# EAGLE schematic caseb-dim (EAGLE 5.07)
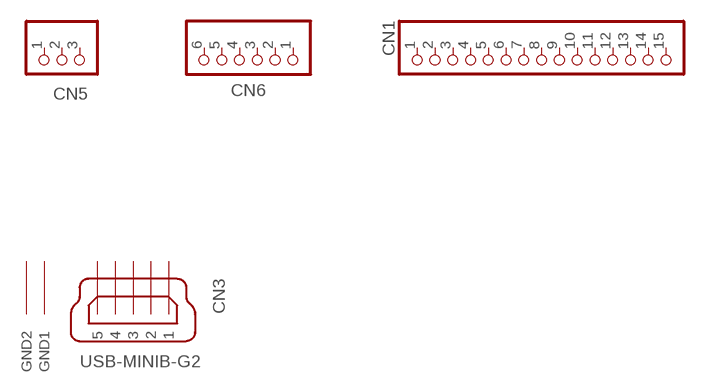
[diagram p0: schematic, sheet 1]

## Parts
CN1  PINHDR15  [PINHDRX15]
CN3  USB-MINIB-G2  [USB-MINIBV]
CN5  PINHDR3  [PINHDR1X3]
CN6  PINHDR6  [PINHDR1X6]
Unconnected: CN1.1 CN1.2 CN1.3 CN1.4 CN1.5 CN1.6 CN1.7 CN1.8 CN1.9 CN1.10 CN1.11 CN1.12 CN1.13 CN1.14 CN1.15 CN3.1 CN3.2 CN3.3 CN3.4 CN3.5 CN3.M1(GND1) CN3.M2(GND2) CN5.1 CN5.2 CN5.3 CN6.1 CN6.2 CN6.3 CN6.4 CN6.5 CN6.6

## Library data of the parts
CN1 = SRT162-010:PINHDR15
CN3 = SRT162-010:USB-MINIB-G2
CN5 = SRT162-010:PINHDR3
CN6 = SRT162-010:PINHDR6

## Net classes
0 default: width 0.203 mm
1 power: width 0.254 mm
